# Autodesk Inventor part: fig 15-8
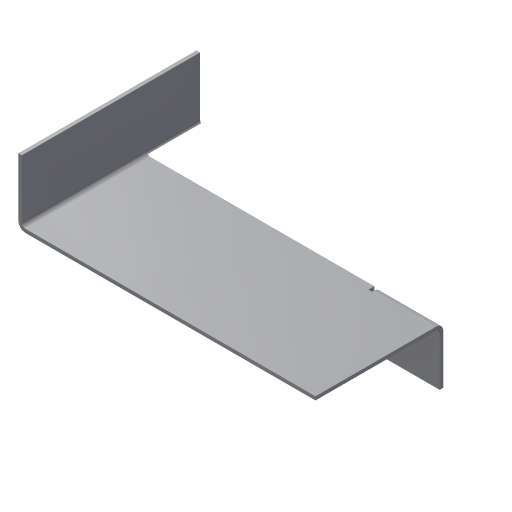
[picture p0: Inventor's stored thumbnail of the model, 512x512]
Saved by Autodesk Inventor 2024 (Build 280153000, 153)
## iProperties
Shininess: 77.0
Angle Display Precision: 2
Document Length Units: 11269
Document Angle Units: 11279
Document Time Units: 11290
Document Mass Units: 11283
Document Length Units Precision: 3
Document Angle Units Precision: 2
Created: 2002-04
Part Number: fig 15-8
Material: Aluminum-6061
Document SubType Name: Sheet Metal
Density: 1 g/cm^3
Sheet Metal Rule: Default
Appearance: Aluminum - Flat-1
Density: 0.0
Volumn: 0.0
Area: 0.0
PropertySet Name: Model Information
Control State: 0
Master: False
Checked Out: False
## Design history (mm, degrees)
node "Face1"
  sketch "Sketch1"
    geometry: L1 (-49.559, 19.574)-(-49.559, -30.426); L2 (-49.559, -30.426)-(50.441, -30.426); L3 (50.441, -30.426)-(50.441, 19.574); L4 (50.441, 19.574)-(32.941, 19.574); L5 (32.941, 19.574)-(32.941, 4.574); L6 (32.941, 4.574)-(-32.059, 4.574); L7 (-32.059, 4.574)-(-32.059, 19.574); L8 (-32.059, 19.574)-(-49.559, 19.574)
    constraints: 16 end point, 6 parallel, 2 equal length, 1 perpendicular, 1 vertical
    dimensions: "d0" = 100 distance of L1.end L2.end; "d1" = 65 distance of L5.end L6.end; "d2" = 15 distance of L6.end L7.end; "d3" = 50 distance of L1.start L1.end
feature "Fold2" dims "d8" = 1 (= BendRadius), "d9" = 90 deg, "d10" = 1 (= BendRadius), "d14" = 1 (= BendReliefWidth), "d15" = 0.5 (= BendReliefDepth), "d16" = 2 (= MinimumRemnant), "d20" = 1 (= Thickness), "SeamGap" = 0.01
feature "Fold3" dims "d11" = 1 (= BendRadius), "d12" = 90 deg, "d13" = 1 (= BendRadius), "d17" = 1 (= BendReliefWidth), "d18" = 0.5 (= BendReliefDepth), "d19" = 2 (= MinimumRemnant), "d20" = 1 (= Thickness), "SeamGap" = 0.01
body "Solid1"
sketch "Sketch2"
  geometry: L1 (100, 0)-(0, 0) reference; L2 (17.5, 50)-(17.5, 35) reference; L3 (82.5, 50)-(82.5, 0)
  constraints: 2 end point, 1 parallel, 1 point on line
face "Plate1" dims "d20" = 1 (= Thickness)
sketch "Sketch3"
  geometry: L1 (81.369, -50)-(0, -50) reference; L2 (17.5, 0)-(17.5, -50)
  constraints: 2 end point, 1 perpendicular, 1 point on line
sketch "Sketch4"
  geometry: L1 (17.5, 0)-(17.5, -50) reference; L2 (-63.869, -15)-(0, -15) reference; L3 (0, -15)-(17.5, -15)
  constraints: 2 end point, 1 collinear, 1 point on line
other parameters: "Thickness" = 1, "BendRadius" = 1 (= Thickness), "BendReliefWidth" = 1 (= Thickness), "BendReliefDepth" = 0.5 (= 0.5 x Thickness), "CornerReliefSize" = 4 (= 4 x Thickness), "MinimumRemnant" = 2 (= 2 x Thickness), "TransitionRadius" = 1 (= BendRadius), "d4" = 1 (= BendRadius), "JacobiRadiusSize" = 1 (= Thickness), "GapSize" = 1 (= Thickness)
